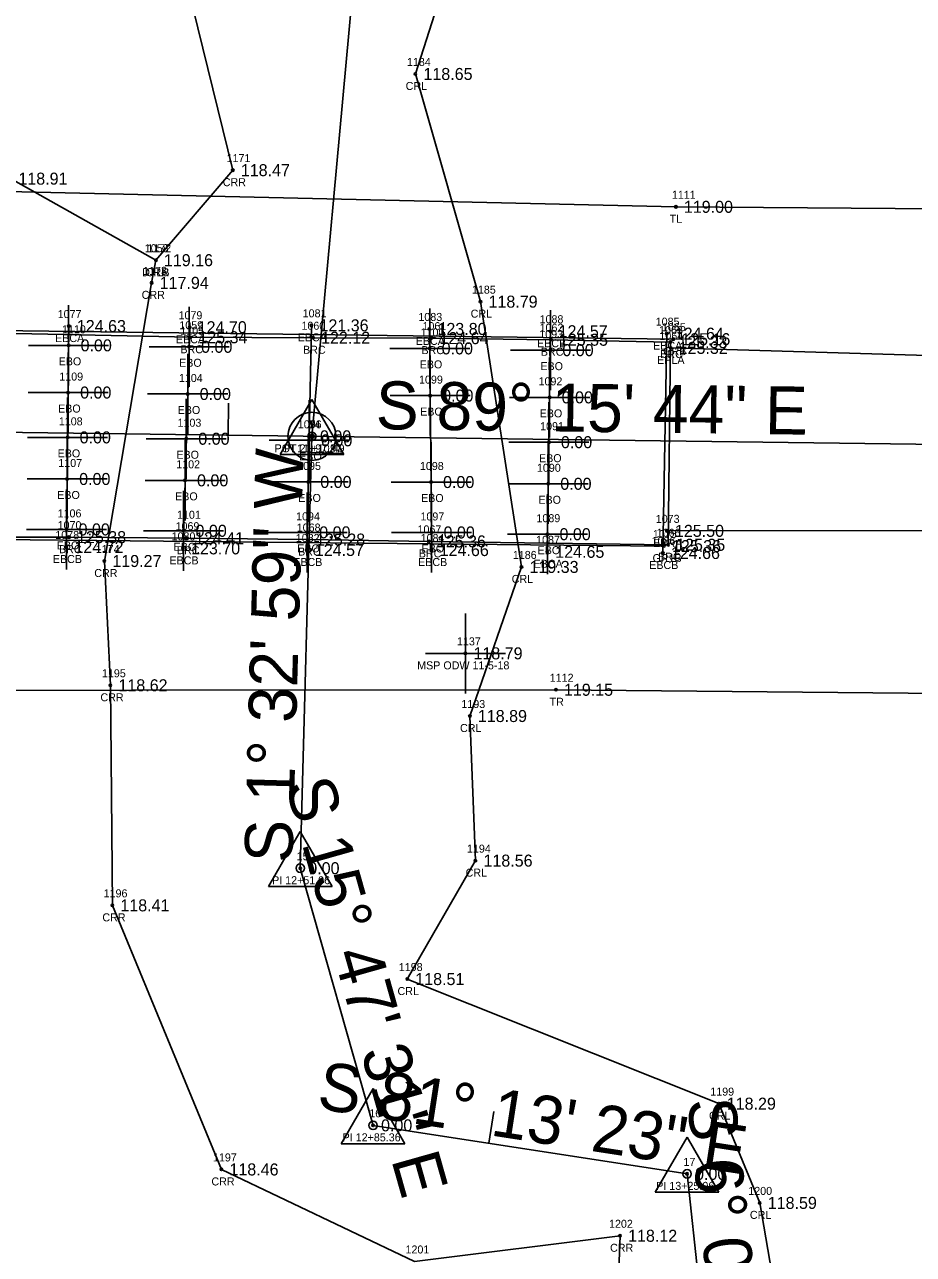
# Model space of a CAD drawing. Extents: x 2374510 to 2377726, y 1024129 to 1025429.
# Drawn here: x 2376481.1 to 2376592.2, y 1024824.9 to 1024978.6 of the extents above; entities that cross this region are included whole.
import ezdxf

# ---------------------------------------------------------------- set-up
doc = ezdxf.new("R2010")
doc.units = 0
for name, color, linetype in [('RD_EX_Bridge', 7, 'Continuous'), ('RD_EX_Bridge_txCode', 7, 'Continuous'), ('RD_EX_GuardRail', 7, 'Continuous'), ('RD_EX_GuardRail_txCode', 7, 'Continuous'), ('RD_EX_H2O', 7, 'Continuous'), ('RD_EX_H2O_txCode', 7, 'Continuous'), ('RD_EX_Road', 7, 'Continuous'), ('RD_EX_Road_txCode', 7, 'Continuous'), ('RD_EX_TX_Bridge_ELEV', 7, 'Continuous'), ('RD_EX_TX_GuardRail_ELEV', 7, 'Continuous'), ('RD_EX_TX_H2O_ELEV', 7, 'Continuous'), ('RD_EX_TX_Misc_ELEV', 7, 'Continuous'), ('RD_EX_TX_Road_ELEV', 7, 'Continuous'), ('RD_EX_TX_VEG_ELEV', 7, 'Continuous'), ('RD_EX_VEG', 7, 'Continuous'), ('RD_EX_VEG_txCode', 7, 'Continuous'), ('RD_HC_Cl', 7, 'Continuous'), ('RD_HC_Data', 7, 'Continuous'), ('RD_HC_Data_Tic', 7, 'Continuous'), ('RD_HC_Survey_ELEV', 7, 'Continuous'), ('RD_HC_txCode', 7, 'Continuous'), ('RD_SMD_Locator', 7, 'Continuous')]:
    doc.layers.add(name, color=color, linetype=linetype)

msp = doc.modelspace()

# ---------------------------------------------------------------- linework, layer by layer
at = {"layer": 'RD_EX_Bridge'}
for p, q in [((2376486.62, 1024933.54), (2376486.62, 1024943.54)), ((2376501.68, 1024933.36), (2376501.68, 1024943.36)), ((2376531.74, 1024933.16), (2376531.74, 1024943.16)), ((2376546.82, 1024932.94), (2376546.82, 1024942.94)), ((2376486.65, 1024940.95), (2376486.35, 1024913.34)), ((2376501.75, 1024940.8), (2376500.92, 1024913.17)), ((2376516.97, 1024941.04), (2376516.39, 1024912.97)), ((2376531.71, 1024940.59), (2376531.99, 1024912.96)), ((2376546.43, 1024912.74), (2376546.85, 1024940.3)), ((2376481.62, 1024938.54), (2376491.62, 1024938.54)), ((2376561.36, 1024940), (2376560.87, 1024912.59)), ((2376486.56, 1024927.64), (2376486.56, 1024937.64)), ((2376496.68, 1024938.36), (2376506.68, 1024938.36)), ((2376501.5, 1024927.46), (2376501.5, 1024937.46)), ((2376526.74, 1024938.16), (2376536.74, 1024938.16)), ((2376531.8, 1024927.26), (2376531.8, 1024937.26)), ((2376541.82, 1024937.94), (2376551.82, 1024937.94)), ((2376546.73, 1024927.04), (2376546.73, 1024937.04)), ((2376481.56, 1024932.64), (2376491.56, 1024932.64)), ((2376496.5, 1024932.46), (2376506.5, 1024932.46)), ((2376486.5, 1024922.04), (2376486.5, 1024932.04)), ((2376501.33, 1024921.87), (2376501.33, 1024931.87)), ((2376516.67, 1024921.67), (2376516.67, 1024931.67)), ((2376526.8, 1024932.26), (2376536.8, 1024932.26)), ((2376541.73, 1024932.04), (2376551.73, 1024932.04)), ((2376546.64, 1024921.44), (2376546.64, 1024931.44)), ((2376481.5, 1024927.04), (2376491.5, 1024927.04)), ((2376486.44, 1024916.84), (2376486.44, 1024926.84)), ((2376496.33, 1024926.87), (2376506.33, 1024926.87)), ((2376501.17, 1024916.67), (2376501.17, 1024926.67)), ((2376511.67, 1024926.67), (2376521.67, 1024926.67)), ((2376516.57, 1024916.47), (2376516.57, 1024926.47)), ((2376531.91, 1024916.46), (2376531.91, 1024926.46)), ((2376541.64, 1024926.44), (2376551.64, 1024926.44)), ((2376546.56, 1024916.24), (2376546.56, 1024926.24)), ((2376481.44, 1024921.84), (2376491.44, 1024921.84)), ((2376496.17, 1024921.67), (2376506.17, 1024921.67)), ((2376486.37, 1024910.54), (2376486.37, 1024920.54)), ((2376500.98, 1024910.37), (2376500.98, 1024920.37)), ((2376511.57, 1024921.47), (2376521.57, 1024921.47)), ((2376516.44, 1024910.17), (2376516.44, 1024920.17)), ((2376526.91, 1024921.46), (2376536.91, 1024921.46)), ((2376531.97, 1024910.16), (2376531.97, 1024920.16)), ((2376541.56, 1024921.24), (2376551.56, 1024921.24)), ((2376546.46, 1024909.94), (2376546.46, 1024919.94)), ((2376481.37, 1024915.54), (2376491.37, 1024915.54)), ((2376495.98, 1024915.37), (2376505.98, 1024915.37)), ((2376511.44, 1024915.17), (2376521.44, 1024915.17)), ((2376526.97, 1024915.16), (2376536.97, 1024915.16)), ((2376541.46, 1024914.94), (2376551.46, 1024914.94))]:
    msp.add_line(p, q, dxfattribs=at)
msp.add_lwpolyline([(2376472.07, 1024940.19), (2376501.84, 1024939.55), (2376517.17, 1024939.49), (2376531.96, 1024939.44), (2376546.88, 1024939.24), (2376561.81, 1024938.95), (2376561.53, 1024913.62), (2376531.63, 1024914.04), (2376516.54, 1024914.27), (2376501.4, 1024914.44), (2376486.67, 1024914.57), (2376471.6, 1024914.56), (2376472.07, 1024940.19)], dxfattribs=at)
for centre in [(2376486.62, 1024938.54), (2376501.68, 1024938.36), (2376531.74, 1024938.16), (2376546.82, 1024937.94), (2376486.56, 1024932.64), (2376501.5, 1024932.46), (2376531.8, 1024932.26), (2376546.73, 1024932.04), (2376486.5, 1024927.04), (2376501.33, 1024926.87), (2376516.67, 1024926.67), (2376546.64, 1024926.44), (2376486.44, 1024921.84), (2376501.17, 1024921.67), (2376516.57, 1024921.47), (2376531.91, 1024921.46), (2376546.56, 1024921.24), (2376486.37, 1024915.54), (2376500.98, 1024915.37), (2376516.44, 1024915.17), (2376531.97, 1024915.16), (2376546.46, 1024914.94)]:
    msp.add_circle(centre, 0.15, dxfattribs=at)
at = {"layer": 'RD_EX_GuardRail'}
for p, q in [((2376471.94, 1024940.47), (2376562.17, 1024939.31)), ((2376471.33, 1024914.36), (2376561.01, 1024913.45))]:
    msp.add_line(p, q, dxfattribs=at)
at = {"layer": 'RD_EX_H2O'}
for p, q in [((2376536.21, 1024895.05), (2376536.21, 1024905.05)), ((2376531.21, 1024900.05), (2376541.21, 1024900.05))]:
    msp.add_line(p, q, dxfattribs=at)
for points in [[(2376522.68, 1025124.28), (2376539.95, 1025091.93), (2376552.99, 1025053.79), (2376555.76, 1025047.24), (2376554.71, 1025040.88), (2376557.55, 1025026.68), (2376555.84, 1025015.85), (2376539.15, 1025001.14), (2376529.96, 1024972.45), (2376538.09, 1024944), (2376543.21, 1024910.85), (2376536.76, 1024892.22), (2376537.46, 1024874.15), (2376528.94, 1024859.35), (2376567.86, 1024843.78), (2376572.98, 1024831.38), (2376577.78, 1024803.44)], [(2376497.97, 1025114.18), (2376509.68, 1025107.56), (2376520.38, 1025090.17), (2376509.44, 1025080.09), (2376513.03, 1025070.01), (2376506.1, 1025057.18), (2376504.25, 1025038.92), (2376503.57, 1025008.7), (2376502.14, 1024980.74), (2376507.14, 1024960.43), (2376497.53, 1024949.18), (2376497, 1024946.35), (2376491.09, 1024911.59), (2376491.85, 1024896.06), (2376492.09, 1024868.56), (2376505.72, 1024835.56), (2376529.83, 1024824.06), (2376555.53, 1024827.27), (2376554.79, 1024808.22)], [(2376415.87, 1024960.14), (2376422.46, 1024965.91), (2376479.35, 1024959.37), (2376497.53, 1024949.18)]]:
    msp.add_lwpolyline(points, dxfattribs=at)
msp.add_circle((2376536.21, 1024900.05), 0.15, dxfattribs=at)
at = {"layer": 'RD_EX_Road'}
for points in [[(2376561.85, 1024938.22), (2376659.62, 1024935.3), (2376763.51, 1024933.89), (2376865.73, 1024932.88), (2376965.35, 1024932.49), (2377065.13, 1024930.78), (2377114.03, 1024930.18), (2377167.22, 1024930.19), (2377217.07, 1024931.12)], [(2376561.38, 1024915.36), (2376658.71, 1024915.48), (2376761.9, 1024913.76), (2376865.54, 1024912.46), (2376965.34, 1024911.98), (2377063.07, 1024911.1), (2377113.55, 1024910.69), (2377167.38, 1024909.96), (2377217.4, 1024910.82)]]:
    msp.add_lwpolyline(points, dxfattribs=at)
at = {"layer": 'RD_EX_VEG'}
for points in [[(2375821.28, 1024948.02), (2375920.08, 1024958.54), (2375972.69, 1024962.41), (2376124.69, 1024965.87), (2376562.5, 1024955.85), (2376666.61, 1024955.06), (2377217.56, 1024949.87)], [(2375819.71, 1024889.63), (2375920.06, 1024900.35), (2376123.72, 1024895.17), (2376547.52, 1024895.5), (2377115.53, 1024890.13), (2377218, 1024892.46)]]:
    msp.add_lwpolyline(points, dxfattribs=at)
at = {"layer": 'RD_HC_Cl'}
for p, q in [((2376531.81, 1025089.31), (2376517.03, 1024927.17)), ((2376010.95, 1024933.69), (2377093.47, 1024919.75)), ((2376517.03, 1024927.17), (2376515.57, 1024873.2)), ((2376515.57, 1024873.2), (2376524.66, 1024841.07)), ((2376524.66, 1024841.07), (2376563.9, 1024835.01)), ((2376563.9, 1024835.01), (2376567.3, 1024803.39))]:
    msp.add_line(p, q, dxfattribs=at)
at = {"layer": 'RD_HC_Data'}
for p, q in [((2376513.06, 1024924.88), (2376517.03, 1024931.76)), ((2376517.03, 1024931.76), (2376521, 1024924.88)), ((2376513.06, 1024924.88), (2376521, 1024924.88)), ((2376511.6, 1024870.91), (2376515.57, 1024877.79)), ((2376515.57, 1024877.79), (2376519.54, 1024870.91)), ((2376511.6, 1024870.91), (2376519.54, 1024870.91)), ((2376520.69, 1024838.78), (2376524.66, 1024845.66)), ((2376524.66, 1024845.66), (2376528.63, 1024838.78)), ((2376520.69, 1024838.78), (2376528.63, 1024838.78)), ((2376559.92, 1024832.72), (2376563.9, 1024839.6)), ((2376563.9, 1024839.6), (2376567.87, 1024832.72)), ((2376559.92, 1024832.72), (2376567.87, 1024832.72))]:
    msp.add_line(p, q, dxfattribs=at)
for centre, radius in [((2376517.03, 1024927.17), 3), ((2376517.03, 1024927.17), 0.529), ((2376517.03, 1024927.17), 0.282), ((2376515.57, 1024873.2), 0.529), ((2376524.66, 1024841.07), 0.529), ((2376563.9, 1024835.01), 0.529)]:
    msp.add_circle(centre, radius, dxfattribs=at)
at = {"layer": 'RD_HC_Data_Tic'}
for p, q in [((2376506.54, 1024927.31), (2376506.59, 1024931.31)), ((2376516.98, 1024925.15), (2376520.98, 1024925.04)), ((2376539.13, 1024838.83), (2376539.74, 1024842.79))]:
    msp.add_line(p, q, dxfattribs=at)
at = {"layer": 'RD_SMD_Locator'}
for centre in [(2376529.96, 1024972.45), (2376507.14, 1024960.43), (2376562.5, 1024955.85), (2376497.53, 1024949.18), (2376497.53, 1024949.18), (2376497, 1024946.35), (2376538.09, 1024944), (2376486.65, 1024940.95), (2376501.75, 1024940.8), (2376516.97, 1024941.04), (2376531.71, 1024940.59), (2376546.85, 1024940.3), (2376561.36, 1024940), (2376486.62, 1024938.54), (2376501.84, 1024939.55), (2376517.17, 1024939.49), (2376531.96, 1024939.44), (2376546.88, 1024939.24), (2376561.81, 1024938.95), (2376562.17, 1024939.31), (2376501.68, 1024938.36), (2376531.74, 1024938.16), (2376546.82, 1024937.94), (2376561.85, 1024938.22), (2376486.56, 1024932.64), (2376501.5, 1024932.46), (2376531.8, 1024932.26), (2376546.73, 1024932.04), (2376486.5, 1024927.04), (2376501.33, 1024926.87), (2376516.67, 1024926.67), (2376517.03, 1024927.17), (2376517.03, 1024927.17), (2376546.64, 1024926.44), (2376486.44, 1024921.84), (2376501.17, 1024921.67), (2376516.57, 1024921.47), (2376531.91, 1024921.46), (2376546.56, 1024921.24), (2376486.37, 1024915.54), (2376500.98, 1024915.37), (2376561.38, 1024915.36), (2376486.67, 1024914.57), (2376501.4, 1024914.44), (2376516.44, 1024915.17), (2376516.54, 1024914.27), (2376531.63, 1024914.04), (2376531.97, 1024915.16), (2376546.46, 1024914.94), (2376486.35, 1024913.34), (2376500.92, 1024913.17), (2376516.39, 1024912.97), (2376531.99, 1024912.96), (2376546.43, 1024912.74), (2376560.87, 1024912.59), (2376561.01, 1024913.45), (2376561.53, 1024913.62), (2376491.09, 1024911.59), (2376543.21, 1024910.85), (2376491.85, 1024896.06), (2376547.52, 1024895.5), (2376536.76, 1024892.22), (2376537.46, 1024874.15), (2376515.57, 1024873.2), (2376492.09, 1024868.56), (2376528.94, 1024859.35), (2376567.86, 1024843.78), (2376524.66, 1024841.07), (2376505.72, 1024835.56), (2376563.9, 1024835.01), (2376572.98, 1024831.38), (2376555.53, 1024827.27)]:
    msp.add_circle(centre, 0.15, dxfattribs=at)

# ---------------------------------------------------------------- texts
at = {"layer": 'RD_EX_Bridge_txCode'}
for s, p in [('1077', (2376485.26, 1024941.95)), ('1079', (2376500.36, 1024941.8)), ('1081', (2376515.87, 1024942.04)), ('1083', (2376530.33, 1024941.59)), ('1088', (2376545.47, 1024941.3)), ('1085', (2376559.98, 1024941)), ('1110', (2376485.8, 1024940.04)), ('1059', (2376500.46, 1024940.55)), ('1105', (2376500.57, 1024939.86)), ('1060', (2376515.72, 1024940.49)), ('1100', (2376530.6, 1024939.66)), ('1061', (2376530.84, 1024940.44)), ('1093', (2376545.43, 1024939.44)), ('1062', (2376545.47, 1024940.24)), ('1063', (2376560.4, 1024939.95)), ('EBCA', (2376484.93, 1024938.95)), ('EBCA', (2376500.03, 1024938.8)), ('BRC', (2376500.59, 1024937.55)), ('EBCA', (2376515.25, 1024939.04)), ('EBCA', (2376530, 1024938.59)), ('EBCB', (2376545.15, 1024938.3)), ('EBCA', (2376559.65, 1024938)), ('EBO', (2376485.38, 1024936.04)), ('BRC', (2376515.92, 1024937.49)), ('BRC', (2376530.71, 1024937.44)), ('BRC', (2376545.63, 1024937.24)), ('BRC', (2376560.55, 1024936.95)), ('EBO', (2376500.43, 1024935.86)), ('EBO', (2376530.49, 1024935.66)), ('EBO', (2376545.57, 1024935.44)), ('1109', (2376485.46, 1024934.14)), ('1104', (2376500.4, 1024933.96)), ('1099', (2376530.41, 1024933.76)), ('1092', (2376545.34, 1024933.54)), ('EBO', (2376485.31, 1024930.14)), ('EBO', (2376500.25, 1024929.96)), ('1108', (2376485.4, 1024928.54)), ('1103', (2376500.23, 1024928.37)), ('EBO', (2376530.55, 1024929.76)), ('EBO', (2376545.48, 1024929.54)), ('1096', (2376515.26, 1024928.17)), ('1091', (2376545.54, 1024927.94)), ('EBO', (2376485.25, 1024924.54)), ('EBO', (2376500.09, 1024924.37)), ('EBO', (2376515.43, 1024924.17)), ('EBO', (2376545.4, 1024923.94)), ('1107', (2376485.34, 1024923.34)), ('1102', (2376500.07, 1024923.17)), ('1095', (2376515.18, 1024922.97)), ('1098', (2376530.52, 1024922.96)), ('1090', (2376545.14, 1024922.74)), ('EBO', (2376485.2, 1024919.34)), ('EBO', (2376499.93, 1024919.17)), ('EBO', (2376515.32, 1024918.97)), ('EBO', (2376530.66, 1024918.96)), ('EBO', (2376545.32, 1024918.74)), ('1106', (2376485.25, 1024917.04)), ('1101', (2376500.17, 1024916.87)), ('1094', (2376515.05, 1024916.67)), ('1097', (2376530.59, 1024916.66)), ('1089', (2376545.08, 1024916.44)), ('1070', (2376485.25, 1024915.57)), ('1069', (2376499.99, 1024915.44)), ('1068', (2376515.13, 1024915.27)), ('1067', (2376530.22, 1024915.04)), ('1066', (2376560.1, 1024914.62)), ('1078', (2376484.96, 1024914.34)), ('EBO', (2376485.13, 1024913.04)), ('1080', (2376499.49, 1024914.17)), ('1082', (2376515.01, 1024913.97)), ('1084', (2376530.61, 1024913.96)), ('1087', (2376545.04, 1024913.74)), ('1086', (2376559.46, 1024913.59)), ('BRC', (2376485.42, 1024912.57)), ('EBO', (2376499.74, 1024912.87)), ('BRC', (2376500.15, 1024912.44)), ('EBO', (2376515.19, 1024912.67)), ('BRC', (2376515.29, 1024912.27)), ('BRC', (2376530.38, 1024912.04)), ('EBO', (2376530.73, 1024912.66)), ('EBO', (2376545.22, 1024912.44)), ('BRC', (2376560.28, 1024911.62)), ('EBCB', (2376484.65, 1024911.34)), ('EBCB', (2376499.22, 1024911.17)), ('EBCB', (2376514.69, 1024910.97)), ('EBCB', (2376530.29, 1024910.96)), ('EBCA', (2376544.71, 1024910.74)), ('EBCB', (2376559.17, 1024910.59))]:
    msp.add_text(s, height=1, dxfattribs=at).set_placement(p)
at = {"layer": 'RD_EX_GuardRail_txCode'}
for s, p in [('1065', (2376560.76, 1024940.31)), ('GRB', (2376560.92, 1024937.31)), ('1075', (2376559.62, 1024914.45)), ('GR1B', (2376559.59, 1024911.45))]:
    msp.add_text(s, height=1, dxfattribs=at).set_placement(p)
at = {"layer": 'RD_EX_H2O_txCode'}
for s, p in [('1184', (2376528.9, 1024973.45)), ('CRL', (2376528.74, 1024970.45)), ('1171', (2376506.36, 1024961.43)), ('CRR', (2376505.89, 1024958.43)), ('1058', (2376496.14, 1024950.18)), ('1172', (2376496.46, 1024950.18)), ('DTLB', (2376495.81, 1024947.18)), ('1173', (2376495.93, 1024947.35)), ('CRR', (2376496.27, 1024947.18)), ('CRR', (2376495.75, 1024944.35)), ('1185', (2376537.02, 1024945)), ('CRL', (2376536.86, 1024942)), ('1174', (2376490.02, 1024912.59)), ('1186', (2376542.13, 1024911.85)), ('CRR', (2376489.83, 1024909.59)), ('CRL', (2376541.99, 1024908.85)), ('1137', (2376535.15, 1024901.05)), ('MSP ODW 11-5-18', (2376530.18, 1024898.05)), ('1195', (2376490.79, 1024897.06)), ('CRR', (2376490.6, 1024894.06)), ('1193', (2376535.7, 1024893.22)), ('CRL', (2376535.53, 1024890.22)), ('1194', (2376536.4, 1024875.15)), ('CRL', (2376536.23, 1024872.15)), ('1196', (2376491, 1024869.56)), ('CRR', (2376490.84, 1024866.56)), ('1198', (2376527.88, 1024860.35)), ('CRL', (2376527.72, 1024857.35)), ('1199', (2376566.8, 1024844.78)), ('CRL', (2376566.64, 1024841.78)), ('1197', (2376504.66, 1024836.56)), ('CRR', (2376504.47, 1024833.56)), ('1200', (2376571.55, 1024832.38)), ('CRL', (2376571.75, 1024829.38)), ('1202', (2376554.15, 1024828.27)), ('1201', (2376528.72, 1024825.06)), ('CRR', (2376554.28, 1024825.27))]:
    msp.add_text(s, height=1, dxfattribs=at).set_placement(p)
at = {"layer": 'RD_EX_Road_txCode'}
for s, p in [('1064', (2376560.44, 1024939.22)), ('EPLA', (2376560.16, 1024936.22)), ('1073', (2376559.99, 1024916.36)), ('EPRA', (2376559.66, 1024913.36))]:
    msp.add_text(s, height=1, dxfattribs=at).set_placement(p)
at = {"layer": 'RD_EX_TX_Bridge_ELEV'}
for s, p in [('124.63', (2376487.65, 1024940.2)), ('121.36', (2376517.97, 1024940.29)), ('124.70', (2376502.75, 1024940.05)), ('125.34', (2376502.84, 1024938.8)), ('122.12', (2376518.17, 1024938.74)), ('123.80', (2376532.71, 1024939.84)), ('124.64', (2376532.96, 1024938.69)), ('124.57', (2376547.85, 1024939.55)), ('124.64', (2376562.36, 1024939.25)), ('0.00', (2376488.12, 1024937.79)), ('0.00', (2376503.18, 1024937.61)), ('0.00', (2376533.24, 1024937.41)), ('125.35', (2376547.88, 1024938.49)), ('0.00', (2376548.32, 1024937.19)), ('125.33', (2376562.81, 1024938.2)), ('0.00', (2376488.06, 1024931.89)), ('0.00', (2376503, 1024931.71)), ('0.00', (2376533.3, 1024931.51)), ('0.00', (2376548.23, 1024931.29)), ('0.00', (2376488, 1024926.29)), ('0.00', (2376502.83, 1024926.12)), ('0.00', (2376518.17, 1024925.92)), ('0.00', (2376548.14, 1024925.69)), ('0.00', (2376487.94, 1024921.09)), ('0.00', (2376502.67, 1024920.92)), ('0.00', (2376518.07, 1024920.72)), ('0.00', (2376533.41, 1024920.71)), ('0.00', (2376548.06, 1024920.49)), ('0.00', (2376487.87, 1024914.79)), ('0.00', (2376502.48, 1024914.62)), ('0.00', (2376517.94, 1024914.42)), ('0.00', (2376533.47, 1024914.41)), ('0.00', (2376547.96, 1024914.19)), ('124.72', (2376487.35, 1024912.59)), ('125.38', (2376487.67, 1024913.82)), ('123.70', (2376501.92, 1024912.42)), ('124.41', (2376502.4, 1024913.69)), ('125.28', (2376517.54, 1024913.52)), ('125.36', (2376532.63, 1024913.29)), ('125.35', (2376562.53, 1024912.87)), ('124.57', (2376517.39, 1024912.22)), ('124.66', (2376532.99, 1024912.21)), ('124.65', (2376547.43, 1024911.99)), ('124.66', (2376561.87, 1024911.84))]:
    msp.add_text(s, height=1.5, dxfattribs=at).set_placement(p)
at = {"layer": 'RD_EX_TX_GuardRail_ELEV'}
for s, p in [('125.16', (2376563.17, 1024938.56)), ('125.36', (2376562.01, 1024912.7))]:
    msp.add_text(s, height=1.5, dxfattribs=at).set_placement(p)
at = {"layer": 'RD_EX_TX_H2O_ELEV'}
for s, p in [('118.65', (2376530.96, 1024971.7)), ('118.91', (2376480.35, 1024958.62)), ('118.47', (2376508.14, 1024959.68)), ('119.16', (2376498.53, 1024948.43)), ('119.16', (2376498.53, 1024948.43)), ('117.94', (2376498, 1024945.6)), ('118.79', (2376539.09, 1024943.25)), ('119.27', (2376492.09, 1024910.84)), ('119.33', (2376544.21, 1024910.1)), ('118.62', (2376492.85, 1024895.31)), ('118.89', (2376537.76, 1024891.47)), ('118.56', (2376538.46, 1024873.4)), ('118.41', (2376493.09, 1024867.81)), ('118.51', (2376529.94, 1024858.6)), ('118.29', (2376568.86, 1024843.03)), ('118.46', (2376506.72, 1024834.81)), ('118.59', (2376573.98, 1024830.63)), ('118.12', (2376556.53, 1024826.52))]:
    msp.add_text(s, height=1.5, dxfattribs=at).set_placement(p)
at = {"layer": 'RD_EX_TX_Misc_ELEV'}
msp.add_text('118.79', height=1.5, dxfattribs=at).set_placement((2376537.21, 1024899.3))
at = {"layer": 'RD_EX_TX_Road_ELEV'}
for s, p in [('125.32', (2376562.85, 1024937.47)), ('125.50', (2376562.38, 1024914.61))]:
    msp.add_text(s, height=1.5, dxfattribs=at).set_placement(p)
at = {"layer": 'RD_EX_TX_VEG_ELEV'}
for s, p in [('119.00', (2376563.5, 1024955.1)), ('119.15', (2376548.52, 1024894.75))]:
    msp.add_text(s, height=1.5, dxfattribs=at).set_placement(p)
at = {"layer": 'RD_EX_VEG_txCode'}
for s, p in [('1111', (2376562, 1024956.85)), ('TL', (2376561.73, 1024953.85)), ('1112', (2376546.74, 1024896.5)), ('TR', (2376546.72, 1024893.5))]:
    msp.add_text(s, height=1, dxfattribs=at).set_placement(p)
at = {"layer": 'RD_HC_Data'}
for s, rotation, p in [('S 89%%d 15\' 44" E', 359.2623, (2376524.98, 1024928.07)), ('S 1%%d 32\' 59" W', 88.4501, (2376514.59, 1024873.84)), ('S 15%%d 47\' 31" E', 285.7919, (2376513.67, 1024883.62)), ('S 81%%d 13\' 23" E', 351.223, (2376517.51, 1024843.18)), ('S 6%%d 08\' 27" E', 276.1409, (2376563.91, 1024844.2))]:
    msp.add_text(s, height=6, rotation=rotation, dxfattribs=at).set_placement(p)
at = {"layer": 'RD_HC_Survey_ELEV'}
for p in [(2376518.03, 1024926.42), (2376518.03, 1024926.42), (2376516.57, 1024872.45), (2376525.66, 1024840.32), (2376564.9, 1024834.26)]:
    msp.add_text('0.00', height=1.5, dxfattribs=at).set_placement(p)
at = {"layer": 'RD_HC_txCode'}
for s, p in [('14', (2376516.58, 1024928.17)), ('7', (2376516.75, 1024928.17)), ('POT 21+10.49', (2376512.36, 1024925.17)), ('PI 11+97.97', (2376513.54, 1024925.17)), ('15', (2376515.12, 1024874.2)), ('PI 12+51.96', (2376512.05, 1024871.2)), ('16', (2376524.19, 1024842.07)), ('PI 12+85.36', (2376520.86, 1024839.07)), ('17', (2376563.45, 1024836.01)), ('PI 13+25.06', (2376560.05, 1024833.01))]:
    msp.add_text(s, height=1, dxfattribs=at).set_placement(p)

doc.saveas('drawing.dxf')
